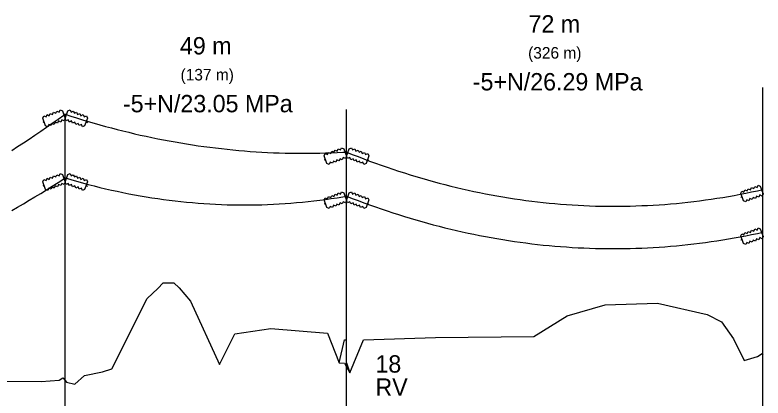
# Model space of a CAD drawing. Extents: x -21 to 1873, y 784 to 994.
# Drawn here: x 1378 to 1507.2, y 916.1 to 982.3 of the extents above; entities that cross this region are included whole.
import ezdxf

# ---------------------------------------------------------------- set-up
doc = ezdxf.new("R2010")
doc.units = 0
for name, color, linetype in [('Vrstva 11', 7, 'Continuous'), ('Vrstva 12', 7, 'Continuous'), ('Vrstva 13', 7, 'Continuous'), ('Vrstva 14', 7, 'Continuous'), ('Vrstva 15', 7, 'Continuous'), ('Vrstva 29', 7, 'Continuous'), ('Vrstva 3', 7, 'Continuous')]:
    doc.layers.add(name, color=color, linetype=linetype)

msp = doc.modelspace()

# ---------------------------------------------------------------- linework, layer by layer
at = {"layer": 'Vrstva 11'}
for points in [[(1377.43, 958.94), (1378.43, 959.59), (1379.43, 960.24), (1380.43, 960.9), (1381.43, 961.57), (1382.43, 962.24), (1383.43, 962.93), (1384.43, 963.62), (1385.43, 964.32), (1386.43, 965.02), (1386.64, 965.17)], [(1386.64, 965.17), (1387.64, 964.85), (1388.64, 964.54), (1389.64, 964.23), (1390.64, 963.93), (1391.64, 963.64), (1392.64, 963.36), (1393.64, 963.08), (1394.64, 962.81), (1395.64, 962.55), (1396.64, 962.3), (1397.64, 962.06), (1398.64, 961.82), (1399.64, 961.59), (1400.64, 961.37), (1401.64, 961.16), (1402.64, 960.96), (1403.64, 960.76), (1404.64, 960.57), (1405.64, 960.39), (1406.64, 960.22), (1407.64, 960.06), (1408.64, 959.9), (1409.64, 959.75), (1410.64, 959.61), (1411.64, 959.48), (1412.64, 959.35), (1413.64, 959.24), (1414.64, 959.13), (1415.64, 959.03), (1416.64, 958.93), (1417.64, 958.85), (1418.64, 958.77), (1419.64, 958.7), (1420.64, 958.64), (1421.64, 958.59), (1422.64, 958.54), (1423.64, 958.51), (1424.64, 958.48), (1425.64, 958.45), (1426.64, 958.44), (1427.64, 958.43), (1428.64, 958.44), (1429.64, 958.45), (1430.64, 958.46), (1431.64, 958.49), (1432.64, 958.52), (1433.64, 958.57), (1434.64, 958.62), (1435.26, 958.65)], [(1435.26, 958.65), (1436.26, 958.25), (1437.26, 957.86), (1438.26, 957.47), (1439.26, 957.1), (1440.26, 956.73), (1441.26, 956.38), (1442.26, 956.03), (1443.26, 955.69), (1444.26, 955.36), (1445.26, 955.04), (1446.26, 954.72), (1447.26, 954.42), (1448.26, 954.12), (1449.26, 953.83), (1450.26, 953.56), (1451.26, 953.29), (1452.26, 953.03), (1453.26, 952.77), (1454.26, 952.53), (1455.26, 952.3), (1456.26, 952.07), (1457.26, 951.85), (1458.26, 951.65), (1459.26, 951.45), (1460.26, 951.26), (1461.26, 951.07), (1462.26, 950.9), (1463.26, 950.74), (1464.26, 950.58), (1465.26, 950.44), (1466.26, 950.3), (1467.26, 950.17), (1468.26, 950.05), (1469.26, 949.94), (1470.26, 949.83), (1471.26, 949.74), (1472.26, 949.65), (1473.26, 949.58), (1474.26, 949.51), (1475.26, 949.45), (1476.26, 949.4), (1477.26, 949.36), (1478.26, 949.32), (1479.26, 949.3), (1480.26, 949.29), (1481.26, 949.28), (1482.26, 949.28), (1483.26, 949.29), (1484.26, 949.31), (1485.26, 949.34), (1486.26, 949.38), (1487.26, 949.42), (1488.26, 949.48), (1489.26, 949.54), (1490.26, 949.61), (1491.26, 949.69), (1492.26, 949.78), (1493.26, 949.88), (1494.26, 949.99), (1495.26, 950.11), (1496.26, 950.23), (1497.26, 950.37), (1498.26, 950.51), (1499.26, 950.66), (1500.26, 950.82), (1501.26, 950.99), (1502.26, 951.16), (1503.26, 951.35), (1504.26, 951.55), (1505.26, 951.75), (1506.26, 951.96), (1507.22, 952.18)], [(1377.43, 948.57), (1378.43, 949.14), (1379.43, 949.72), (1380.43, 950.31), (1381.43, 950.9), (1382.43, 951.51), (1383.43, 952.13), (1384.43, 952.76), (1385.43, 953.39), (1386.43, 954.04), (1386.64, 954.17)], [(1386.64, 954.17), (1387.64, 953.88), (1388.64, 953.59), (1389.64, 953.31), (1390.64, 953.05), (1391.64, 952.79), (1392.64, 952.54), (1393.64, 952.3), (1394.64, 952.08), (1395.64, 951.86), (1396.64, 951.65), (1397.64, 951.45), (1398.64, 951.26), (1399.64, 951.08), (1400.64, 950.91), (1401.64, 950.75), (1402.64, 950.6), (1403.64, 950.46), (1404.64, 950.33), (1405.64, 950.21), (1406.64, 950.1), (1407.64, 949.99), (1408.64, 949.9), (1409.64, 949.82), (1410.64, 949.75), (1411.64, 949.68), (1412.64, 949.63), (1413.64, 949.59), (1414.64, 949.55), (1415.64, 949.53), (1416.64, 949.51), (1417.64, 949.51), (1418.64, 949.51), (1419.64, 949.53), (1420.64, 949.55), (1421.64, 949.59), (1422.64, 949.63), (1423.64, 949.68), (1424.64, 949.75), (1425.64, 949.82), (1426.64, 949.9), (1427.64, 950), (1428.64, 950.1), (1429.64, 950.21), (1430.64, 950.33), (1431.64, 950.46), (1432.64, 950.61), (1433.64, 950.76), (1434.64, 950.92), (1435.26, 951.02)], [(1435.26, 951.02), (1436.26, 950.63), (1437.26, 950.25), (1438.26, 949.88), (1439.26, 949.52), (1440.26, 949.16), (1441.26, 948.82), (1442.26, 948.48), (1443.26, 948.15), (1444.26, 947.83), (1445.26, 947.52), (1446.26, 947.21), (1447.26, 946.92), (1448.26, 946.63), (1449.26, 946.35), (1450.26, 946.08), (1451.26, 945.82), (1452.26, 945.57), (1453.26, 945.33), (1454.26, 945.09), (1455.26, 944.86), (1456.26, 944.65), (1457.26, 944.44), (1458.26, 944.23), (1459.26, 944.04), (1460.26, 943.86), (1461.26, 943.68), (1462.26, 943.51), (1463.26, 943.36), (1464.26, 943.21), (1465.26, 943.06), (1466.26, 942.93), (1467.26, 942.81), (1468.26, 942.69), (1469.26, 942.58), (1470.26, 942.48), (1471.26, 942.39), (1472.26, 942.31), (1473.26, 942.24), (1474.26, 942.17), (1475.26, 942.12), (1476.26, 942.07), (1477.26, 942.03), (1478.26, 942), (1479.26, 941.98), (1480.26, 941.96), (1481.26, 941.96), (1482.26, 941.96), (1483.26, 941.97), (1484.26, 941.99), (1485.26, 942.02), (1486.26, 942.06), (1487.26, 942.1), (1488.26, 942.16), (1489.26, 942.22), (1490.26, 942.29), (1491.26, 942.37), (1492.26, 942.46), (1493.26, 942.56), (1494.26, 942.66), (1495.26, 942.78), (1496.26, 942.9), (1497.26, 943.03), (1498.26, 943.17), (1499.26, 943.32), (1500.26, 943.47), (1501.26, 943.64), (1502.26, 943.81), (1503.26, 943.99), (1504.26, 944.19), (1505.26, 944.38), (1506.26, 944.59), (1507.22, 944.8)]]:
    msp.add_lwpolyline(points, dxfattribs=at)
at = {"layer": 'Vrstva 14'}
for p, q in [((1507.22, 893.8), (1507.22, 969.8)), ((1435.26, 891.52), (1435.26, 966.02)), ((1386.64, 889.17), (1386.64, 965.17))]:
    msp.add_line(p, q, dxfattribs=at)
at = {"layer": 'Vrstva 29'}
for points in [[(1386.17, 965.75), (1386.64, 964.43), (1386.47, 964.05), (1386.08, 964.23), (1385.9, 963.84), (1385.52, 964.02), (1385.34, 963.64), (1384.95, 963.82), (1384.77, 963.43), (1384.39, 963.61), (1384.21, 963.23), (1383.83, 963.41), (1383.65, 963.02), (1383.26, 963.2), (1382.78, 964.52), (1382.96, 964.9), (1383.35, 964.72), (1383.53, 965.11), (1383.91, 964.93), (1384.09, 965.31), (1384.47, 965.13), (1384.65, 965.52), (1385.04, 965.34), (1385.22, 965.72), (1385.6, 965.54), (1385.78, 965.93)], [(1386.64, 964.43), (1387.11, 965.75), (1387.5, 965.93), (1387.68, 965.54), (1388.06, 965.72), (1388.24, 965.34), (1388.63, 965.52), (1388.81, 965.13), (1389.19, 965.31), (1389.37, 964.93), (1389.75, 965.11), (1389.93, 964.72), (1390.32, 964.9), (1390.5, 964.52), (1390.02, 963.2), (1389.63, 963.02), (1389.46, 963.41), (1389.07, 963.23), (1388.89, 963.61), (1388.51, 963.43), (1388.33, 963.82), (1387.94, 963.64), (1387.76, 964.02), (1387.38, 963.84), (1387.2, 964.23), (1386.82, 964.05)], [(1434.79, 959.22), (1435.27, 957.91), (1435.09, 957.52), (1434.7, 957.7), (1434.52, 957.32), (1434.14, 957.5), (1433.96, 957.11), (1433.58, 957.29), (1433.4, 956.91), (1433.01, 957.09), (1432.83, 956.7), (1432.45, 956.88), (1432.27, 956.5), (1431.88, 956.68), (1431.41, 957.99), (1431.58, 958.38), (1431.97, 958.2), (1432.15, 958.58), (1432.53, 958.4), (1432.71, 958.79), (1433.1, 958.61), (1433.28, 958.99), (1433.66, 958.81), (1433.84, 959.2), (1434.22, 959.02), (1434.4, 959.4)], [(1435.26, 957.91), (1435.74, 959.22), (1436.12, 959.4), (1436.3, 959.02), (1436.69, 959.2), (1436.86, 958.81), (1437.25, 958.99), (1437.43, 958.61), (1437.81, 958.79), (1437.99, 958.4), (1438.38, 958.58), (1438.56, 958.2), (1438.94, 958.38), (1439.12, 957.99), (1438.64, 956.68), (1438.26, 956.5), (1438.08, 956.88), (1437.69, 956.7), (1437.51, 957.09), (1437.13, 956.91), (1436.95, 957.29), (1436.57, 957.11), (1436.39, 957.5), (1436, 957.32), (1435.82, 957.7), (1435.44, 957.52)], [(1386.17, 954.75), (1386.64, 953.43), (1386.47, 953.05), (1386.08, 953.23), (1385.9, 952.84), (1385.52, 953.02), (1385.34, 952.64), (1384.95, 952.82), (1384.77, 952.43), (1384.39, 952.61), (1384.21, 952.23), (1383.83, 952.41), (1383.65, 952.02), (1383.26, 952.2), (1382.78, 953.52), (1382.96, 953.9), (1383.35, 953.72), (1383.53, 954.11), (1383.91, 953.93), (1384.09, 954.31), (1384.47, 954.13), (1384.65, 954.52), (1385.04, 954.34), (1385.22, 954.72), (1385.6, 954.54), (1385.78, 954.93)], [(1386.64, 953.43), (1387.11, 954.75), (1387.5, 954.93), (1387.68, 954.54), (1388.06, 954.72), (1388.24, 954.34), (1388.63, 954.52), (1388.81, 954.13), (1389.19, 954.31), (1389.37, 953.93), (1389.75, 954.11), (1389.93, 953.72), (1390.32, 953.9), (1390.5, 953.52), (1390.02, 952.2), (1389.63, 952.02), (1389.46, 952.41), (1389.07, 952.23), (1388.89, 952.61), (1388.51, 952.43), (1388.33, 952.82), (1387.94, 952.64), (1387.76, 953.02), (1387.38, 952.84), (1387.2, 953.23), (1386.82, 953.05)], [(1506.75, 952.75), (1507.23, 951.43), (1507.05, 951.05), (1506.66, 951.23), (1506.49, 950.84), (1506.1, 951.02), (1505.92, 950.64), (1505.54, 950.82), (1505.36, 950.43), (1504.97, 950.61), (1504.79, 950.23), (1504.41, 950.41), (1504.23, 950.02), (1503.85, 950.2), (1503.37, 951.52), (1503.55, 951.9), (1503.93, 951.72), (1504.11, 952.11), (1504.49, 951.93), (1504.67, 952.31), (1505.06, 952.13), (1505.24, 952.52), (1505.62, 952.34), (1505.8, 952.72), (1506.19, 952.54), (1506.37, 952.93)], [(1434.79, 951.59), (1435.27, 950.28), (1435.09, 949.89), (1434.7, 950.07), (1434.52, 949.69), (1434.14, 949.87), (1433.96, 949.48), (1433.58, 949.66), (1433.4, 949.28), (1433.01, 949.46), (1432.83, 949.07), (1432.45, 949.25), (1432.27, 948.87), (1431.88, 949.05), (1431.41, 950.36), (1431.58, 950.75), (1431.97, 950.57), (1432.15, 950.95), (1432.53, 950.77), (1432.71, 951.16), (1433.1, 950.98), (1433.28, 951.36), (1433.66, 951.18), (1433.84, 951.57), (1434.22, 951.39), (1434.4, 951.77)], [(1435.26, 950.28), (1435.74, 951.59), (1436.12, 951.77), (1436.3, 951.39), (1436.69, 951.57), (1436.86, 951.18), (1437.25, 951.36), (1437.43, 950.98), (1437.81, 951.16), (1437.99, 950.77), (1438.38, 950.95), (1438.56, 950.57), (1438.94, 950.75), (1439.12, 950.36), (1438.64, 949.05), (1438.26, 948.87), (1438.08, 949.25), (1437.69, 949.07), (1437.51, 949.46), (1437.13, 949.28), (1436.95, 949.66), (1436.57, 949.48), (1436.39, 949.87), (1436, 949.69), (1435.82, 950.07), (1435.44, 949.89)], [(1506.75, 945.37), (1507.23, 944.06), (1507.05, 943.67), (1506.66, 943.85), (1506.49, 943.47), (1506.1, 943.65), (1505.92, 943.26), (1505.54, 943.44), (1505.36, 943.06), (1504.97, 943.24), (1504.79, 942.85), (1504.41, 943.03), (1504.23, 942.65), (1503.85, 942.83), (1503.37, 944.14), (1503.55, 944.53), (1503.93, 944.35), (1504.11, 944.73), (1504.49, 944.55), (1504.67, 944.94), (1505.06, 944.76), (1505.24, 945.14), (1505.62, 944.96), (1505.8, 945.35), (1506.19, 945.17), (1506.37, 945.55)]]:
    msp.add_lwpolyline(points, close=True, dxfattribs=at)
for points in [[(1386.64, 965.17), (1386.41, 965.09)], [(1386.64, 965.17), (1386.88, 965.09)], [(1383.02, 963.86), (1382.79, 963.77)], [(1390.26, 963.86), (1390.49, 963.77)], [(1435.26, 958.65), (1435.03, 958.56)], [(1435.26, 958.65), (1435.5, 958.56)], [(1431.65, 957.33), (1431.41, 957.25)], [(1438.88, 957.33), (1439.12, 957.25)], [(1386.64, 954.17), (1386.41, 954.09)], [(1386.64, 954.17), (1386.88, 954.09)], [(1383.02, 952.86), (1382.79, 952.77)], [(1390.26, 952.86), (1390.49, 952.77)], [(1507.22, 952.18), (1506.99, 952.09)], [(1435.26, 951.02), (1435.03, 950.94)], [(1435.26, 951.02), (1435.5, 950.94)], [(1503.61, 950.86), (1503.37, 950.77)], [(1431.65, 949.7), (1431.41, 949.62)], [(1438.88, 949.7), (1439.12, 949.62)], [(1507.22, 944.8), (1506.99, 944.71)], [(1503.61, 943.48), (1503.37, 943.4)]]:
    msp.add_lwpolyline(points, dxfattribs=at)
at = {"layer": 'Vrstva 3'}
for p, q in [((1402.66, 935.05), (1403.6, 936.05)), ((1402.66, 935.05), (1403.6, 936.05)), ((1403.6, 936.05), (1405.42, 936.05)), ((1403.6, 936.05), (1405.42, 936.05)), ((1405.42, 936.05), (1406.37, 935.2)), ((1405.42, 936.05), (1406.37, 935.2)), ((1400.81, 933.35), (1402.66, 935.05)), ((1400.81, 933.35), (1402.66, 935.05)), ((1406.37, 935.2), (1408.33, 932.9)), ((1406.37, 935.2), (1408.33, 932.9)), ((1394.73, 921.2), (1400.81, 933.35)), ((1394.73, 921.2), (1400.81, 933.35)), ((1408.33, 932.9), (1413.31, 921.9)), ((1408.33, 932.9), (1413.31, 921.9)), ((1473.36, 930.35), (1479.95, 932.25)), ((1473.36, 930.35), (1479.95, 932.25)), ((1479.95, 932.25), (1489, 932.5)), ((1479.95, 932.25), (1489, 932.5)), ((1489, 932.5), (1497.59, 930.55)), ((1489, 932.5), (1497.59, 930.55)), ((1467.6, 926.75), (1473.36, 930.35)), ((1467.6, 926.75), (1473.36, 930.35)), ((1497.59, 930.55), (1500.08, 929.3)), ((1497.59, 930.55), (1500.08, 929.3)), ((1500.08, 929.3), (1502.1, 926.35)), ((1500.08, 929.3), (1502.1, 926.35)), ((1415.94, 927.25), (1422.2, 928.15)), ((1415.94, 927.25), (1422.2, 928.15)), ((1422.2, 928.15), (1431.95, 927.35)), ((1422.2, 928.15), (1431.95, 927.35)), ((1413.31, 921.9), (1415.94, 927.25)), ((1413.31, 921.9), (1415.94, 927.25)), ((1431.95, 927.35), (1434.01, 922.2)), ((1431.95, 927.35), (1434.01, 922.2)), ((1450.65, 926.6), (1467.6, 926.75)), ((1450.65, 926.6), (1467.6, 926.75)), ((1434.01, 922.2), (1434.91, 926.2)), ((1434.91, 926.2), (1435.26, 926.2)), ((1435.84, 920.5), (1438.19, 926.2)), ((1435.84, 920.5), (1438.19, 926.2)), ((1438.19, 926.2), (1450.65, 926.6)), ((1438.19, 926.2), (1450.65, 926.6)), ((1502.1, 926.35), (1503.96, 922.6)), ((1502.1, 926.35), (1503.96, 922.6)), ((1503.96, 922.6), (1506.25, 923.3)), ((1503.96, 922.6), (1506.25, 923.3)), ((1506.25, 923.3), (1507.09, 923.8)), ((1506.25, 923.3), (1507.09, 923.8)), ((1507.09, 923.8), (1507.22, 923.8)), ((1507.09, 923.8), (1507.22, 923.68)), ((1434.01, 922.2), (1434.91, 922.15)), ((1434.91, 922.15), (1435.26, 921.52)), ((1435.26, 922.15), (1435.26, 922.2)), ((1435.26, 922.2), (1435.84, 920.5)), ((1390.02, 920), (1393.11, 920.65)), ((1390.02, 920), (1393.11, 920.65)), ((1393.11, 920.65), (1394.73, 921.2)), ((1393.11, 920.65), (1394.73, 921.2)), ((1435.26, 921.52), (1435.84, 920.5)), ((1362.95, 919.1), (1382.48, 919)), ((1362.95, 919.1), (1382.48, 919)), ((1382.48, 919), (1385.63, 919.2)), ((1382.48, 919), (1385.63, 919.2)), ((1385.63, 919.2), (1386.26, 919.6)), ((1385.63, 919.2), (1386.26, 919.6)), ((1386.26, 919.6), (1386.64, 919.17)), ((1386.26, 919.6), (1386.64, 919.17)), ((1386.64, 919.17), (1386.89, 918.9)), ((1386.64, 919.17), (1386.89, 918.9)), ((1388.35, 918.5), (1390.02, 920)), ((1388.35, 918.5), (1390.02, 920)), ((1386.89, 918.9), (1388.35, 918.5)), ((1386.89, 918.9), (1388.35, 918.5))]:
    msp.add_line(p, q, dxfattribs=at)

# ---------------------------------------------------------------- texts
at = {"layer": 'Vrstva 12'}
for s, p in [('-5+N/26.29 MPa', (1457.08, 969.3)), ('-5+N/23.05 MPa', (1396.64, 965.52))]:
    msp.add_text(s, height=3, dxfattribs=at).set_placement(p)
at = {"layer": 'Vrstva 13'}
for s, height, p in [('72 m', 3, (1466.71, 979.3)), ('49 m', 3, (1406.48, 975.52)), ('(326 m)', 2, (1466.64, 974.8)), ('(137 m)', 2, (1406.59, 971.02))]:
    msp.add_text(s, height=height, dxfattribs=at).set_placement(p)
at = {"layer": 'Vrstva 15'}
for s, p in [('18', (1440.26, 920.52)), ('RV', (1440.26, 916.52))]:
    msp.add_text(s, height=3, dxfattribs=at).set_placement(p)

doc.saveas('drawing.dxf')
